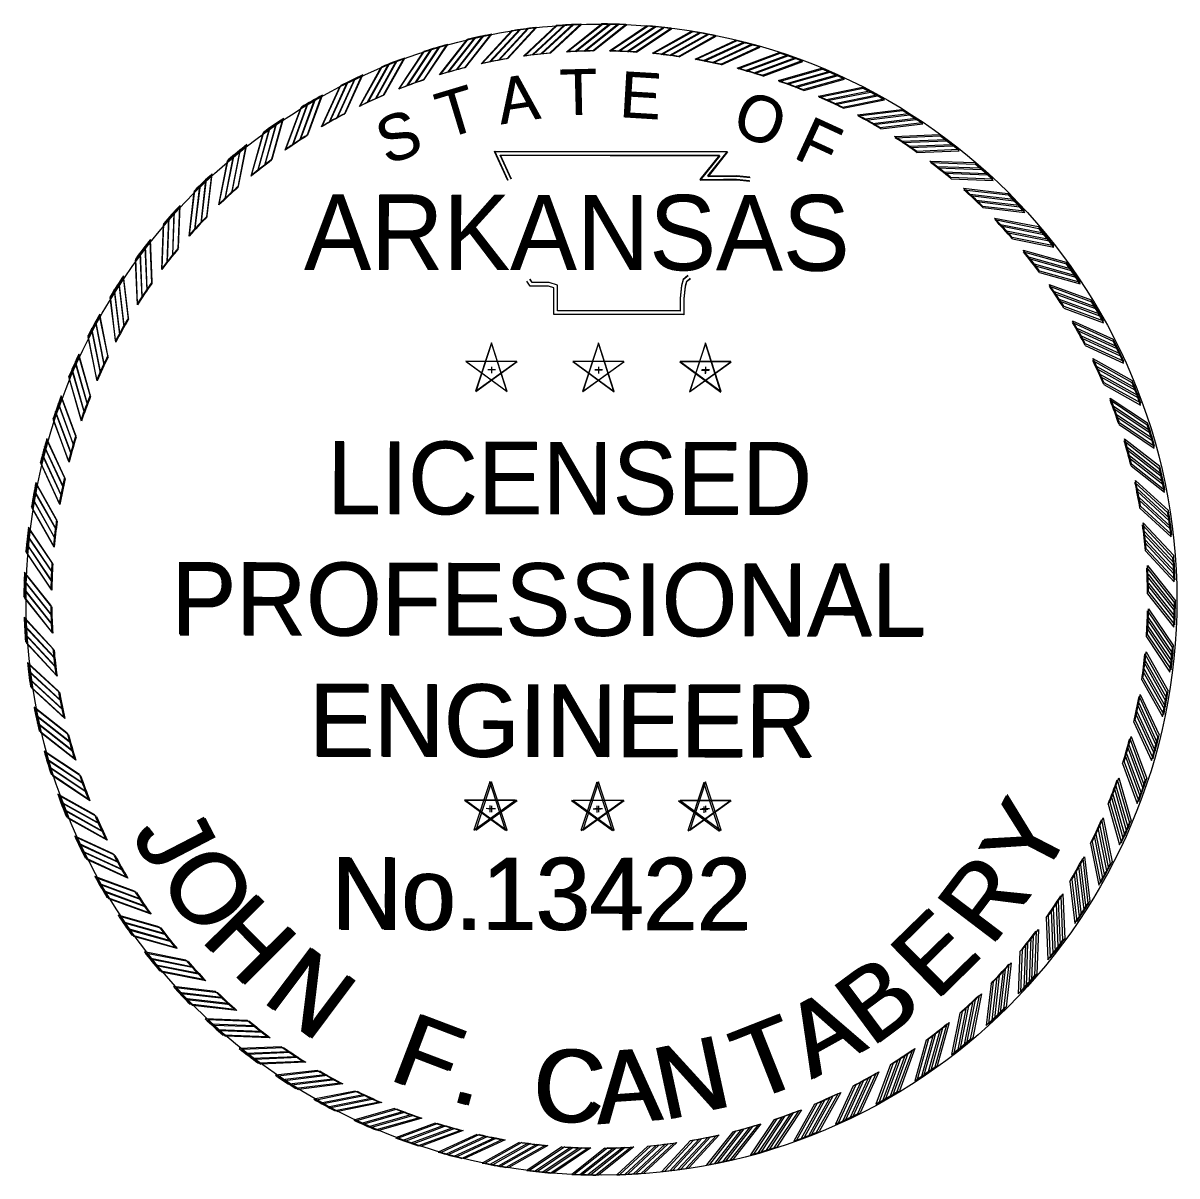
# Model space of a CAD drawing. Extents: x 0 to 19, y -0.6 to 11.2.
# Drawn here: x 17.82 to 19.023, y 7.715 to 8.916 of the extents above; entities that cross this region are included whole.
import ezdxf

# ---------------------------------------------------------------- set-up
doc = ezdxf.new("R2010")
doc.units = 0
for name, color, linetype in [('Default', 7, 'Continuous'), ('G-ANNO-STMP', 7, 'Continuous'), ('G-No Plot-Stamp-1', 7, 'Continuous'), ('G-No Plot-Stamp-2', 7, 'Continuous')]:
    doc.layers.add(name, color=color, linetype=linetype)

# ---------------------------------------------------------------- blocks, each defined once
blk = doc.blocks.new('STAR')
at = {"layer": 'Default'}
for p, q in [((-0.0001, 0.0615), (-0.0366, -0.0504)), ((0.0362, -0.0503), (0, 0.0617)), ((0.0587, 0.0188), (-0.059, 0.0189)), ((-0.0589, 0.0188), (0.0363, -0.0505)), ((-0.0365, -0.0503), (0.0589, 0.0188)), ((-0.0085, 0), (0.009, 0)), ((0, 0.0063), (0, -0.0085))]:
    blk.add_line(p, q, dxfattribs=at)
blk = doc.blocks.new('RP')
at = {"layer": 'Default'}
for p, q in [((-0.0781, 1.2656), (0.003, 1.33)), ((-0.058, 1.2667), (0.0216, 1.3299)), ((-0.0375, 1.2674), (0.0405, 1.3294)), ((-0.0176, 1.2679), (0.059, 1.3287))]:
    blk.add_line(p, q, dxfattribs=at)
for radius, start, end in [(1.33, 87.4562, 89.8699), (1.268, 90.7933, 93.5307)]:
    blk.add_arc((0, 0), radius, start, end, dxfattribs=at)

msp = doc.modelspace()

# ---------------------------------------------------------------- linework, layer by layer
at = {"layer": 'G-ANNO-STMP'}
for points in [[(18.3256, 8.7521), (18.3116, 8.7824), (18.5542, 8.7826), (18.5339, 8.7571), (18.5504, 8.7573), (18.5641, 8.7575), (18.5779, 8.756)], [(18.3261, 8.7522), (18.3121, 8.7827), (18.5547, 8.782), (18.5344, 8.7566), (18.5509, 8.7567), (18.5646, 8.7569), (18.5784, 8.7553)], [(18.3291, 8.7537), (18.3176, 8.7786), (18.5462, 8.7787), (18.5258, 8.7532), (18.5504, 8.7535), (18.564, 8.7537), (18.5775, 8.7522)], [(18.3295, 8.7538), (18.3181, 8.7788), (18.5468, 8.7781), (18.5263, 8.7526), (18.5509, 8.7529), (18.5644, 8.753), (18.5779, 8.7515)], [(18.5135, 8.6534), (18.5084, 8.6492), (18.5066, 8.6427), (18.5052, 8.6296), (18.5052, 8.6165), (18.3775, 8.6165), (18.3775, 8.6353), (18.3775, 8.6432), (18.3687, 8.6459), (18.3509, 8.6459), (18.3487, 8.6493)], [(18.5136, 8.6529), (18.5085, 8.6488), (18.5067, 8.6423), (18.5053, 8.6292), (18.5052, 8.6161), (18.3775, 8.6165), (18.3775, 8.6353), (18.3776, 8.6432), (18.3688, 8.6459), (18.3511, 8.6459), (18.3488, 8.6494)], [(18.5159, 8.6504), (18.5118, 8.647), (18.5104, 8.642), (18.509, 8.6294), (18.509, 8.6127), (18.3736, 8.6127), (18.3736, 8.6353), (18.3736, 8.6403), (18.3681, 8.642), (18.3489, 8.642), (18.3454, 8.6472)], [(18.5161, 8.6499), (18.5119, 8.6466), (18.5105, 8.6415), (18.5091, 8.629), (18.509, 8.6122), (18.3736, 8.6127), (18.3737, 8.6353), (18.3737, 8.6403), (18.3682, 8.642), (18.349, 8.6421), (18.3456, 8.6473)]]:
    msp.add_lwpolyline(points, dxfattribs=at)
at = {"layer": 'G-No Plot-Stamp-1'}
msp.add_circle((18.4233, 8.3154), 0.6, dxfattribs=at)
at = {"layer": 'G-No Plot-Stamp-2'}
msp.add_circle((18.4233, 8.3154), 0.6, dxfattribs=at)

# ---------------------------------------------------------------- block references
at = {"layer": 'G-ANNO-STMP'}
for name, p, xscale, yscale, rotation in [('RP', (18.4219, 8.3156), 0.45103579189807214, 0.4510357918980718, 4.500000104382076), ('RP', (18.4219, 8.3156), 0.451035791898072, 0.45103579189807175, -4.499999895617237), ('RP', (18.4209, 8.3154), 0.4510357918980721, 0.45103579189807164, -4.695800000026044), ('RP', (18.4219, 8.3156), 0.45103579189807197, 0.4510357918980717, 13.500000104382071), ('RP', (18.4209, 8.3154), 0.451035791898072, 0.45103579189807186, 13.304199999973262), ('RP', (18.4219, 8.3156), 0.45103579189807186, 0.45103579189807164, 9.000000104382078), ('RP', (18.4209, 8.3154), 0.4510357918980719, 0.4510357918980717, 8.804199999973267), ('RP', (18.4209, 8.3154), 0.451035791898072, 0.45103579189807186, 4.304199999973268), ('RP', (18.4219, 8.3156), 0.451035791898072, 0.45103579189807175, 1.0438208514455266e-07), ('RP', (18.4209, 8.3154), 0.451035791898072, 0.45103579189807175, -0.19580000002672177), ('RP', (18.4219, 8.3156), 0.4510357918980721, 0.45103579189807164, -8.999999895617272), ('RP', (18.4209, 8.3154), 0.45103579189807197, 0.45103579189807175, -9.195800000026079), ('RP', (18.4219, 8.3156), 0.4510357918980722, 0.45103579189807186, -13.499999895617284), ('RP', (18.4209, 8.3154), 0.4510357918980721, 0.4510357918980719, -13.695800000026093), ('RP', (18.4219, 8.3156), 0.45103579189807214, 0.4510357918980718, 18.000000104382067), ('RP', (18.4209, 8.3154), 0.45103579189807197, 0.4510357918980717, 17.804199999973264), ('RP', (18.4219, 8.3156), 0.45103579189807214, 0.4510357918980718, -17.99999989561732), ('RP', (18.4209, 8.3154), 0.4510357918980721, 0.4510357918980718, -18.19580000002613), ('RP', (18.4219, 8.3156), 0.45103579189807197, 0.45103579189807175, 22.500000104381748), ('RP', (18.4209, 8.3154), 0.451035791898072, 0.4510357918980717, 22.304199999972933), ('RP', (18.4219, 8.3156), 0.4510357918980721, 0.4510357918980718, -22.499999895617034), ('RP', (18.4209, 8.3154), 0.45103579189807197, 0.4510357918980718, -22.695800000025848), ('RP', (18.4219, 8.3156), 0.451035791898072, 0.45103579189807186, 27.000000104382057), ('RP', (18.4209, 8.3154), 0.45103579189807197, 0.4510357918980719, 26.804199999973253), ('RP', (18.4219, 8.3156), 0.45103579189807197, 0.4510357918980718, -26.999999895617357), ('RP', (18.4209, 8.3154), 0.45103579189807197, 0.45103579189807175, -27.19580000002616), ('RP', (18.4219, 8.3156), 0.45103579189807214, 0.45103579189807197, -31.499999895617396), ('RP', (18.4209, 8.3154), 0.4510357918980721, 0.45103579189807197, -31.695800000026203), ('RP', (18.4219, 8.3156), 0.45103579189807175, 0.45103579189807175, 31.50000010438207), ('RP', (18.4209, 8.3154), 0.4510357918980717, 0.4510357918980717, 31.30419999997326), ('RP', (18.4219, 8.3156), 0.4510357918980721, 0.451035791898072, -35.999999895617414), ('RP', (18.4209, 8.3154), 0.451035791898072, 0.45103579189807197, -36.195800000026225), ('RP', (18.4219, 8.3156), 0.4510357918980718, 0.45103579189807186, 36.00000010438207), ('RP', (18.4209, 8.3154), 0.4510357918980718, 0.45103579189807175, 35.80419999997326), ('RP', (18.4219, 8.3156), 0.4510357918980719, 0.45103579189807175, 40.50000010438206), ('RP', (18.4209, 8.3154), 0.45103579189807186, 0.45103579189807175, 40.30419999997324), ('RP', (18.4219, 8.3156), 0.45103579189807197, 0.451035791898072, -40.49999989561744), ('RP', (18.4209, 8.3154), 0.45103579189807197, 0.45103579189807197, -40.69580000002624), ('RP', (18.4209, 8.3154), 0.45103579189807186, 0.45103579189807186, 44.80419999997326), ('RP', (18.4219, 8.3156), 0.45103579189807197, 0.45103579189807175, -44.99999989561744), ('RP', (18.4209, 8.3154), 0.4510357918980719, 0.45103579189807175, -45.19580000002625), ('RP', (18.4219, 8.3156), 0.45103579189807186, 0.451035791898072, 45.00000010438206), ('RP', (18.4219, 8.3156), 0.45103579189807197, 0.451035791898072, 49.500000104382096), ('RP', (18.4209, 8.3154), 0.451035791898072, 0.451035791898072, 49.304199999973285), ('RP', (18.4219, 8.3156), 0.4510357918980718, 0.4510357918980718, -49.499999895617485), ('RP', (18.4209, 8.3154), 0.4510357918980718, 0.45103579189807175, -49.695800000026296), ('RP', (18.4219, 8.3156), 0.45103579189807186, 0.4510357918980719, 54.00000010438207), ('RP', (18.4209, 8.3154), 0.4510357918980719, 0.4510357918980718, 53.804199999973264), ('RP', (18.4219, 8.3156), 0.45103579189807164, 0.45103579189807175, -53.999999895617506), ('RP', (18.4209, 8.3154), 0.45103579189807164, 0.4510357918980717, -54.1958000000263), ('RP', (18.4209, 8.3154), 0.45103579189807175, 0.4510357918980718, 58.304199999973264), ('RP', (18.4219, 8.3156), 0.4510357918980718, 0.4510357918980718, 58.50000010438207), ('RP', (18.4219, 8.3156), 0.4510357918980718, 0.4510357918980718, -58.49999989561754), ('RP', (18.4209, 8.3154), 0.45103579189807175, 0.45103579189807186, -58.69580000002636), ('RP', (18.4219, 8.3156), 0.4510357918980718, 0.45103579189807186, -62.99999989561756), ('RP', (18.4209, 8.3154), 0.4510357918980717, 0.4510357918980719, -63.19580000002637), ('RP', (18.4209, 8.3154), 0.45103579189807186, 0.4510357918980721, 62.804199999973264), ('RP', (18.4219, 8.3156), 0.4510357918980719, 0.451035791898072, 63.00000010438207), ('STAR', (18.3085, 8.5553), 0.451035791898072, 0.45103579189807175, -0.19580000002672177), ('STAR', (18.3087, 8.5551), 0.451035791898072, 0.45103579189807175, 1.0438208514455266e-07), ('STAR', (18.4201, 8.5549), 0.451035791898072, 0.45103579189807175, -0.19580000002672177), ('STAR', (18.4203, 8.5551), 0.451035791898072, 0.45103579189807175, 1.0438208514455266e-07), ('STAR', (18.5316, 8.5545), 0.451035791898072, 0.45103579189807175, -0.19580000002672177), ('STAR', (18.5318, 8.5551), 0.451035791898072, 0.45103579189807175, 1.0438208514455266e-07), ('RP', (18.4209, 8.3154), 0.45103579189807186, 0.4510357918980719, 67.30419999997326), ('RP', (18.4219, 8.3156), 0.4510357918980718, 0.45103579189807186, 67.50000010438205), ('RP', (18.4209, 8.3154), 0.4510357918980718, 0.45103579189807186, -67.69580000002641), ('RP', (18.4219, 8.3156), 0.45103579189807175, 0.45103579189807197, -67.49999989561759), ('RP', (18.4209, 8.3154), 0.4510357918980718, 0.4510357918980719, -72.19580000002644), ('RP', (18.4219, 8.3156), 0.4510357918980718, 0.45103579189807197, -71.99999989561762), ('RP', (18.4209, 8.3154), 0.45103579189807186, 0.451035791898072, 71.80419999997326), ('RP', (18.4219, 8.3156), 0.4510357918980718, 0.45103579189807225, 72.00000010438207), ('RP', (18.4209, 8.3154), 0.4510357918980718, 0.4510357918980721, 76.30419999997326), ('RP', (18.4209, 8.3154), 0.4510357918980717, 0.4510357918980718, -76.69580000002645), ('RP', (18.4219, 8.3156), 0.4510357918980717, 0.4510357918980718, -76.49999989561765), ('RP', (18.4219, 8.3156), 0.4510357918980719, 0.451035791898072, 76.50000010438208), ('RP', (18.4209, 8.3154), 0.4510357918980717, 0.45103579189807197, 80.80419999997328), ('RP', (18.4219, 8.3156), 0.4510357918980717, 0.451035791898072, 81.0000001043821), ('RP', (18.4209, 8.3154), 0.4510357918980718, 0.45103579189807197, -81.19580000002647), ('RP', (18.4219, 8.3156), 0.45103579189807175, 0.45103579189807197, -80.99999989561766), ('RP', (18.4209, 8.3154), 0.4510357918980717, 0.4510357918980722, 85.30419999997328), ('RP', (18.4219, 8.3156), 0.4510357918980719, 0.4510357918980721, 85.5000001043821), ('RP', (18.4209, 8.3154), 0.4510357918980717, 0.4510357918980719, -85.69580000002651), ('RP', (18.4219, 8.3156), 0.45103579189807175, 0.4510357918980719, -85.49999989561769), ('RP', (18.4219, 8.3156), 0.4510357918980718, 0.45103579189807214, -89.99999989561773), ('RP', (18.4209, 8.3154), 0.45103579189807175, 0.451035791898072, 89.80419999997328), ('RP', (18.4219, 8.3156), 0.45103579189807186, 0.45103579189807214, 90.0000001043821), ('RP', (18.4209, 8.3154), 0.45103579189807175, 0.451035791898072, -90.19580000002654), ('RP', (18.4209, 8.3154), 0.45103579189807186, 0.451035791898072, -94.69580000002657), ('RP', (18.4219, 8.3156), 0.45103579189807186, 0.451035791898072, -94.49999989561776), ('RP', (18.4209, 8.3154), 0.45103579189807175, 0.4510357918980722, 94.30419999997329), ('RP', (18.4219, 8.3156), 0.45103579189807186, 0.4510357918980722, 94.5000001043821), ('RP', (18.4209, 8.3154), 0.4510357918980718, 0.45103579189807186, 98.8041999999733), ('RP', (18.4209, 8.3154), 0.45103579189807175, 0.45103579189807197, -99.19580000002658), ('RP', (18.4219, 8.3156), 0.4510357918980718, 0.4510357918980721, -98.99999989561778), ('RP', (18.4219, 8.3156), 0.45103579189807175, 0.4510357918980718, 99.0000001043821), ('RP', (18.4209, 8.3154), 0.4510357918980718, 0.4510357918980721, 103.30419999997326), ('RP', (18.4219, 8.3156), 0.45103579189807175, 0.451035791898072, 103.50000010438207), ('RP', (18.4209, 8.3154), 0.4510357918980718, 0.4510357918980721, -103.69580000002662), ('RP', (18.4219, 8.3156), 0.45103579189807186, 0.45103579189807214, -103.49999989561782), ('RP', (18.4209, 8.3154), 0.45103579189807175, 0.45103579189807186, -108.19580000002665), ('RP', (18.4219, 8.3156), 0.4510357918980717, 0.451035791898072, -107.99999989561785), ('RP', (18.4209, 8.3154), 0.45103579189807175, 0.4510357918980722, 107.80419999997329), ('RP', (18.4219, 8.3156), 0.45103579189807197, 0.45103579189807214, 108.0000001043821), ('RP', (18.4209, 8.3154), 0.45103579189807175, 0.45103579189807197, 112.30419999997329), ('RP', (18.4219, 8.3156), 0.4510357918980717, 0.45103579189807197, 112.5000001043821), ('STAR', (18.3069, 8.0978), 0.451035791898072, 0.45103579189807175, -0.19580000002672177), ('STAR', (18.3087, 8.0976), 0.451035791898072, 0.45103579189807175, 1.0438208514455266e-07), ('STAR', (18.4185, 8.0974), 0.451035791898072, 0.45103579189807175, -0.19580000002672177), ('STAR', (18.4203, 8.0976), 0.451035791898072, 0.45103579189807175, 1.0438208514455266e-07), ('STAR', (18.5301, 8.097), 0.451035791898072, 0.45103579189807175, -0.19580000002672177), ('STAR', (18.5318, 8.0976), 0.451035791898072, 0.45103579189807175, 1.0438208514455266e-07), ('RP', (18.4209, 8.3154), 0.4510357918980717, 0.4510357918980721, -112.69580000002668), ('RP', (18.4219, 8.3156), 0.45103579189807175, 0.4510357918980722, -112.49999989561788), ('RP', (18.4209, 8.3154), 0.4510357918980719, 0.4510357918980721, -117.19580000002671), ('RP', (18.4219, 8.3156), 0.451035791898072, 0.4510357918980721, -116.9999998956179), ('RP', (18.4209, 8.3154), 0.4510357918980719, 0.45103579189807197, 116.80419999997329), ('RP', (18.4219, 8.3156), 0.4510357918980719, 0.45103579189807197, 117.0000001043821), ('RP', (18.4209, 8.3154), 0.45103579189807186, 0.45103579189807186, 121.30419999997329), ('RP', (18.4219, 8.3156), 0.45103579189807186, 0.45103579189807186, 121.5000001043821), ('RP', (18.4209, 8.3154), 0.4510357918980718, 0.4510357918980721, -121.69580000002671), ('RP', (18.4219, 8.3156), 0.4510357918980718, 0.4510357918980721, -121.4999998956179), ('RP', (18.4209, 8.3154), 0.45103579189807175, 0.45103579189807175, 125.80419999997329), ('RP', (18.4219, 8.3156), 0.4510357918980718, 0.4510357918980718, 126.00000010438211), ('RP', (18.4209, 8.3154), 0.4510357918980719, 0.45103579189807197, -126.19580000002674), ('RP', (18.4219, 8.3156), 0.45103579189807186, 0.45103579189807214, -125.99999989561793), ('RP', (18.4209, 8.3154), 0.4510357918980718, 0.4510357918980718, 130.3041999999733), ('RP', (18.4209, 8.3154), 0.45103579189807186, 0.45103579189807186, -130.6958000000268), ('RP', (18.4219, 8.3156), 0.45103579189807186, 0.4510357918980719, -130.49999989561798), ('RP', (18.4219, 8.3156), 0.4510357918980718, 0.45103579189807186, 130.50000010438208), ('RP', (18.4209, 8.3154), 0.45103579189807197, 0.45103579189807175, 134.80419999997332), ('RP', (18.4219, 8.3156), 0.45103579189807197, 0.4510357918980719, 135.00000010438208), ('RP', (18.4209, 8.3154), 0.45103579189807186, 0.45103579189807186, -135.19580000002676), ('RP', (18.4219, 8.3156), 0.45103579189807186, 0.451035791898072, -134.99999989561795), ('RP', (18.4209, 8.3154), 0.45103579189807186, 0.45103579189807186, 139.30419999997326), ('RP', (18.4219, 8.3156), 0.4510357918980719, 0.45103579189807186, 139.50000010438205), ('RP', (18.4209, 8.3154), 0.4510357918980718, 0.45103579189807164, -139.69580000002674), ('RP', (18.4219, 8.3156), 0.4510357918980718, 0.45103579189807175, -139.49999989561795), ('RP', (18.4209, 8.3154), 0.451035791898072, 0.45103579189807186, 143.8041999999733), ('RP', (18.4219, 8.3156), 0.4510357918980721, 0.4510357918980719, 144.00000010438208), ('RP', (18.4209, 8.3154), 0.4510357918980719, 0.4510357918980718, -144.19580000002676), ('RP', (18.4219, 8.3156), 0.45103579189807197, 0.45103579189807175, -143.99999989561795), ('RP', (18.4209, 8.3154), 0.45103579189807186, 0.45103579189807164, -148.69580000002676), ('RP', (18.4219, 8.3156), 0.45103579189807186, 0.45103579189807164, -148.49999989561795), ('RP', (18.4209, 8.3154), 0.4510357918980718, 0.45103579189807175, 148.3041999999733), ('RP', (18.4219, 8.3156), 0.4510357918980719, 0.4510357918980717, 148.50000010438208), ('RP', (18.4209, 8.3154), 0.45103579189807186, 0.45103579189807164, -153.1958000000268), ('RP', (18.4219, 8.3156), 0.4510357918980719, 0.4510357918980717, -152.99999989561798), ('RP', (18.4209, 8.3154), 0.4510357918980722, 0.4510357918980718, 152.8041999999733), ('RP', (18.4219, 8.3156), 0.4510357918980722, 0.45103579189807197, 153.00000010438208), ('RP', (18.4209, 8.3154), 0.45103579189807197, 0.4510357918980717, 157.3041999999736), ('RP', (18.4219, 8.3156), 0.4510357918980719, 0.4510357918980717, 157.50000010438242), ('RP', (18.4209, 8.3154), 0.451035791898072, 0.4510357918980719, -157.6958000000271), ('RP', (18.4219, 8.3156), 0.45103579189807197, 0.45103579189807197, -157.4999998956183), ('RP', (18.4209, 8.3154), 0.4510357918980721, 0.4510357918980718, 161.8041999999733), ('RP', (18.4219, 8.3156), 0.4510357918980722, 0.4510357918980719, 162.00000010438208), ('RP', (18.4209, 8.3154), 0.45103579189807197, 0.4510357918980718, -162.19580000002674), ('RP', (18.4219, 8.3156), 0.45103579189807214, 0.45103579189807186, -161.99999989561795), ('RP', (18.4209, 8.3154), 0.4510357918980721, 0.4510357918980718, 166.3041999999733), ('RP', (18.4219, 8.3156), 0.4510357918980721, 0.4510357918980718, 166.50000010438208), ('RP', (18.4209, 8.3154), 0.451035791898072, 0.45103579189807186, -166.69580000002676), ('RP', (18.4219, 8.3156), 0.45103579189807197, 0.4510357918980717, -166.49999989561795), ('RP', (18.4209, 8.3154), 0.45103579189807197, 0.4510357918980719, 170.8041999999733), ('RP', (18.4219, 8.3156), 0.45103579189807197, 0.4510357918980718, 171.00000010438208), ('RP', (18.4209, 8.3154), 0.451035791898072, 0.45103579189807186, 175.3041999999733), ('RP', (18.4219, 8.3156), 0.4510357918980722, 0.4510357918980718, 175.50000010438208), ('RP', (18.4209, 8.3154), 0.45103579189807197, 0.4510357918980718, -175.69580000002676), ('RP', (18.4219, 8.3156), 0.45103579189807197, 0.45103579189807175, -175.49999989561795), ('RP', (18.4209, 8.3154), 0.4510357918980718, 0.4510357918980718, -171.19580000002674), ('RP', (18.4219, 8.3156), 0.45103579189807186, 0.45103579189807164, -170.99999989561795), ('RP', (18.4209, 8.3154), 0.451035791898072, 0.45103579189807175, 179.8041999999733), ('RP', (18.4219, 8.3156), 0.45103579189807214, 0.45103579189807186, -179.99999989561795)]:
    msp.add_blockref(name, p, dxfattribs=dict(at, xscale=xscale, yscale=yscale, rotation=rotation))

# ---------------------------------------------------------------- texts
for s, height, rotation, p in [('T', 0.0479, 1.4789, (18.38, 8.82)), ('T', 0.0479, 1.2831, (18.3807, 8.82)), ('A', 0.0479, 8.6788, (18.3182, 8.8105)), ('A', 0.0479, 8.483, (18.3189, 8.8107)), ('E', 0.0479, 356.672, (18.4412, 8.8185)), ('E', 0.0479, 356.4762, (18.4419, 8.8183)), ('T', 0.0479, 16.9015, (18.2601, 8.7953)), ('T', 0.0479, 16.7057, (18.2607, 8.7957)), ('O', 0.0479, 341.2218, (18.5574, 8.8021)), ('O', 0.0479, 341.026, (18.5581, 8.8015)), ('S', 0.0479, 19.7726, (18.1992, 8.768)), ('S', 0.0479, 19.5768, (18.1998, 8.7686)), ('F', 0.0479, 335.3628, (18.6219, 8.7769)), ('F', 0.0479, 335.167, (18.6225, 8.7761)), ('ARKANSAS', 0.0781, 0, (18.1132, 8.6591)), ('ARKANSAS', 0.0781, 359.8042, (18.1134, 8.66)), ('LICENSED', 0.07561, 359.8042, (18.1368, 8.405)), ('LICENSED', 0.07561, 0, (18.1375, 8.4042)), ('PROFESSIONAL', 0.075612, 359.8042, (17.9743, 8.2791)), ('PROFESSIONAL', 0.075612, 0, (17.9755, 8.2777)), ('ENGINEER', 0.07561, 359.8042, (18.1179, 8.1522)), ('ENGINEER', 0.07561, 0, (18.1195, 8.1513)), ('Y', 0.0756, 62.5392, (18.8819, 8.0186)), ('Y', 0.0756, 62.735, (18.8839, 8.0204)), ('J', 0.0756, 297.2813, (17.9322, 8.0724)), ('J', 0.0756, 297.4771, (17.934, 8.0709)), ('O', 0.0756, 304.1899, (17.959, 8.026)), ('O', 0.0756, 304.3857, (17.961, 8.0246)), ('No.13422', 0.07531, 359.8042, (18.1412, 7.9718)), ('No.13422', 0.07531, 0, (18.1434, 7.9711)), ('R', 0.0756, 52.7437, (18.8291, 7.9521)), ('R', 0.0756, 52.9395, (18.8313, 7.9536)), ('H', 0.0756, 314.7447, (18.0036, 7.9609)), ('H', 0.0756, 314.9405, (18.0058, 7.9596)), ('E', 0.0756, 44.306, (18.7715, 7.8958)), ('E', 0.0756, 44.5018, (18.7739, 7.8971)), ('N', 0.0756, 322.9417, (18.0674, 7.8976)), ('N', 0.0756, 323.1375, (18.0698, 7.8966)), ('B', 0.0756, 36.505, (18.7047, 7.8477)), ('B', 0.0756, 36.7008, (18.7074, 7.8488)), ('A', 0.0756, 28.8562, (18.6419, 7.8147)), ('A', 0.0756, 29.052, (18.6447, 7.8156)), ('F', 0.0756, 339.0288, (18.1994, 7.8157)), ('F', 0.0756, 339.2246, (18.2021, 7.8152)), ('T', 0.0756, 21.4329, (18.5791, 7.791)), ('T', 0.0756, 21.6287, (18.5819, 7.7917)), ('N', 0.0756, 12.0703, (18.4879, 7.7722)), ('N', 0.0756, 12.2661, (18.4907, 7.7726)), ('C', 0.0756, 356.1028, (18.3494, 7.7733)), ('C', 0.0756, 356.2986, (18.3523, 7.7732)), ('A', 0.0756, 3.9092, (18.4187, 7.7683)), ('A', 0.0756, 4.105, (18.4216, 7.7685)), ('.', 0.0756, 344.7037, (18.2639, 7.7934)), ('.', 0.0756, 344.8995, (18.2667, 7.793))]:
    msp.add_text(s, height=height, rotation=rotation, dxfattribs=at).set_placement(p)

doc.saveas('drawing.dxf')
